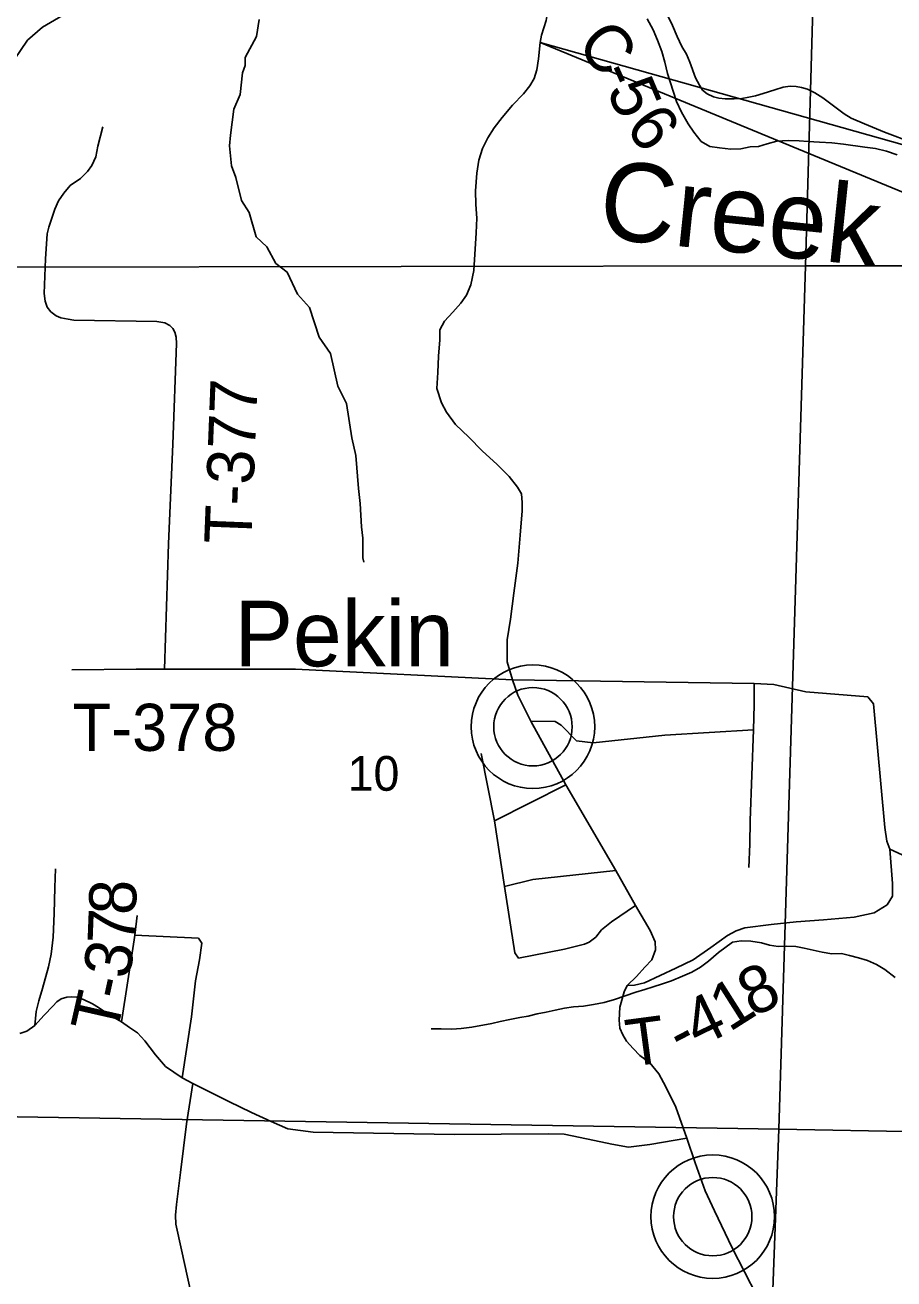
# Model space of a CAD drawing. Extents: x 0 to 34, y 0 to 22.
# Drawn here: x 4.552 to 5.598, y 15.891 to 17.402 of the extents above; entities that cross this region are included whole.
import ezdxf

# ---------------------------------------------------------------- set-up
doc = ezdxf.new("R2010")
doc.units = 0
for name, color, linetype in [('GM_X_County_Road', 7, 'Continuous'), ('GM_X_County_Road_Text', 7, 'Continuous'), ('GM_X_Minor_River', 7, 'Continuous'), ('GM_X_Minor_River_Text', 7, 'Continuous'), ('GM_X_Section', 7, 'Continuous'), ('GM_X_Section_Text', 7, 'Continuous'), ('GM_X_State_Route', 7, 'Continuous'), ('GM_X_Township_Road', 7, 'Continuous'), ('GM_X_Township_Road_Text', 7, 'Continuous'), ('GM_X_Unincorporated', 7, 'Continuous'), ('GM_X_Unincorporated_Location', 7, 'Continuous'), ('GM_X_Unincorporated_Text', 7, 'Continuous'), ('SC_Shading1', 7, 'Continuous'), ('SH_Data', 7, 'Continuous')]:
    doc.layers.add(name, color=color, linetype=linetype)

msp = doc.modelspace()

# ---------------------------------------------------------------- linework, layer by layer
at = {"layer": 'GM_X_County_Road'}
for p, q in [((5.3266, 17.4121), (5.3318, 17.4013)), ((5.3318, 17.4013), (5.3373, 17.3878)), ((5.3373, 17.3878), (5.3428, 17.376)), ((5.3428, 17.376), (5.3484, 17.3665)), ((5.3484, 17.3665), (5.3526, 17.3568)), ((5.3526, 17.3568), (5.3594, 17.3382)), ((5.3594, 17.3382), (5.3641, 17.3291)), ((5.3641, 17.3291), (5.3676, 17.3233)), ((5.3676, 17.3233), (5.3735, 17.3189)), ((5.4407, 17.3191), (5.4548, 17.3238)), ((5.4548, 17.3238), (5.465, 17.3268)), ((5.465, 17.3268), (5.4735, 17.3279)), ((5.4735, 17.3279), (5.4806, 17.3278)), ((5.4806, 17.3278), (5.4868, 17.3266)), ((5.4868, 17.3266), (5.4943, 17.3243)), ((5.4943, 17.3243), (5.503, 17.3201)), ((5.3735, 17.3189), (5.3809, 17.3154)), ((5.3809, 17.3154), (5.3874, 17.3137)), ((5.3874, 17.3137), (5.3949, 17.313)), ((5.3949, 17.313), (5.406, 17.3129)), ((5.406, 17.3129), (5.4152, 17.3134)), ((5.4152, 17.3134), (5.4234, 17.3149)), ((5.4234, 17.3149), (5.4315, 17.3166)), ((5.4315, 17.3166), (5.4407, 17.3191)), ((5.503, 17.3201), (5.5127, 17.3142)), ((5.5127, 17.3142), (5.527, 17.303)), ((5.527, 17.303), (5.5382, 17.2949)), ((5.5382, 17.2949), (5.5467, 17.2894)), ((5.5467, 17.2894), (5.5628, 17.2829)), ((5.5628, 17.2829), (5.5871, 17.2728)), ((5.5871, 17.2728), (5.621, 17.2599)), ((4.5855, 16.2201), (4.5901, 16.2253)), ((4.5901, 16.2253), (4.5956, 16.2287)), ((4.5956, 16.2287), (4.6022, 16.2306)), ((4.6022, 16.2306), (4.6076, 16.2311)), ((4.6076, 16.2311), (4.6145, 16.2308)), ((4.6145, 16.2308), (4.6222, 16.2278)), ((4.6222, 16.2278), (4.6331, 16.2228)), ((4.6331, 16.2228), (4.6403, 16.2184)), ((4.5636, 16.1967), (4.5752, 16.2091)), ((4.5752, 16.2091), (4.5855, 16.2201)), ((4.6403, 16.2184), (4.6539, 16.2093)), ((4.6539, 16.2093), (4.6682, 16.2012)), ((4.5541, 16.19), (4.5636, 16.1967)), ((4.6682, 16.2012), (4.6778, 16.1943)), ((4.6778, 16.1943), (4.6875, 16.1877)), ((4.5459, 16.1869), (4.5541, 16.19)), ((4.6875, 16.1877), (4.6962, 16.1783)), ((4.6962, 16.1783), (4.7092, 16.1614)), ((4.7092, 16.1614), (4.721, 16.1473)), ((4.721, 16.1473), (4.7412, 16.1337)), ((4.7412, 16.1337), (4.7541, 16.127)), ((4.7541, 16.127), (4.7972, 16.1051)), ((4.7972, 16.1051), (4.8247, 16.0918)), ((4.8247, 16.0918), (4.8482, 16.0809)), ((4.8482, 16.0809), (4.8683, 16.0722)), ((4.8683, 16.0722), (4.899, 16.0682)), ((4.899, 16.0682), (5.0689, 16.0652)), ((5.0689, 16.0652), (5.182, 16.0663)), ((5.182, 16.0663), (5.201, 16.0659)), ((5.201, 16.0659), (5.2377, 16.0581)), ((5.2377, 16.0581), (5.2586, 16.0538)), ((5.3045, 16.0533), (5.3491, 16.0608)), ((5.2586, 16.0538), (5.2785, 16.0501)), ((5.2785, 16.0501), (5.3045, 16.0533))]:
    msp.add_line(p, q, dxfattribs=at)
at = {"layer": 'GM_X_Minor_River'}
for p, q in [((4.642, 17.4397), (4.5728, 17.3993)), ((4.5728, 17.3993), (4.5549, 17.3834)), ((4.8338, 17.4082), (4.8308, 17.388)), ((5.3082, 17.3961), (5.301, 17.4092)), ((4.5549, 17.3834), (4.5387, 17.36)), ((4.8308, 17.388), (4.8172, 17.3627)), ((5.3136, 17.3833), (5.3082, 17.3961)), ((5.3189, 17.3698), (5.3136, 17.3833)), ((5.3224, 17.357), (5.3189, 17.3698)), ((4.8172, 17.3627), (4.817, 17.3528)), ((5.3258, 17.3434), (5.3224, 17.357)), ((4.8138, 17.344), (4.8112, 17.318)), ((4.817, 17.3528), (4.8138, 17.344)), ((5.3288, 17.3332), (5.3258, 17.3434)), ((5.3364, 17.3098), (5.3288, 17.3332)), ((4.8112, 17.318), (4.8036, 17.3004)), ((5.3425, 17.2967), (5.3364, 17.3098)), ((4.8036, 17.3004), (4.7992, 17.2691)), ((5.3505, 17.2828), (5.3425, 17.2967)), ((5.3573, 17.2727), (5.3505, 17.2828)), ((4.7992, 17.2691), (4.7983, 17.2562)), ((5.3663, 17.2616), (5.3573, 17.2727)), ((5.4709, 17.2626), (5.4572, 17.2618)), ((5.4842, 17.2622), (5.4709, 17.2626)), ((4.7983, 17.2562), (4.8006, 17.2322)), ((5.3768, 17.2554), (5.3663, 17.2616)), ((5.3882, 17.2539), (5.3768, 17.2554)), ((5.402, 17.2521), (5.3882, 17.2539)), ((5.4141, 17.2528), (5.402, 17.2521)), ((5.4251, 17.2551), (5.4141, 17.2528)), ((5.4353, 17.2554), (5.4251, 17.2551)), ((5.4455, 17.2587), (5.4353, 17.2554)), ((5.4572, 17.2618), (5.4455, 17.2587)), ((5.4949, 17.2614), (5.4842, 17.2622)), ((5.5086, 17.2607), (5.4949, 17.2614)), ((5.5234, 17.2597), (5.5086, 17.2607)), ((5.5375, 17.2582), (5.5234, 17.2597)), ((5.5631, 17.2548), (5.5375, 17.2582)), ((5.5761, 17.2529), (5.5631, 17.2548)), ((5.5895, 17.2496), (5.5761, 17.2529)), ((5.6022, 17.2454), (5.5895, 17.2496)), ((4.8006, 17.2322), (4.8057, 17.2182)), ((4.8057, 17.2182), (4.8126, 17.1905)), ((4.8126, 17.1905), (4.8219, 17.1758)), ((4.8219, 17.1758), (4.8304, 17.1467)), ((4.8304, 17.1467), (4.8431, 17.1347)), ((4.8431, 17.1347), (4.854, 17.1143)), ((4.854, 17.1143), (4.8678, 17.1039)), ((4.8678, 17.1039), (4.8799, 17.0775)), ((4.8799, 17.0775), (4.8946, 17.0613)), ((4.8946, 17.0613), (4.9062, 17.0257)), ((4.9062, 17.0257), (4.9197, 17.0062)), ((4.9197, 17.0062), (4.9287, 16.9667)), ((4.9287, 16.9667), (4.9389, 16.946)), ((4.9389, 16.946), (4.9456, 16.9046)), ((4.9456, 16.9046), (4.9505, 16.8833)), ((4.9505, 16.8833), (4.9535, 16.8434)), ((4.9535, 16.8434), (4.9557, 16.8256)), ((4.9557, 16.8256), (4.9573, 16.7974)), ((4.9573, 16.7974), (4.9587, 16.7837)), ((4.9587, 16.7837), (4.9587, 16.7598)), ((4.9587, 16.7598), (4.9599, 16.7548)), ((5.4039, 16.2971), (5.3872, 16.2847)), ((5.4145, 16.2985), (5.4039, 16.2971)), ((5.4259, 16.2981), (5.4145, 16.2985)), ((5.4389, 16.2963), (5.4259, 16.2981)), ((5.4485, 16.2935), (5.4389, 16.2963)), ((5.3872, 16.2847), (5.375, 16.2741)), ((5.4588, 16.2919), (5.4485, 16.2935)), ((5.4687, 16.2922), (5.4588, 16.2919)), ((5.4801, 16.2918), (5.4687, 16.2922)), ((5.4901, 16.2898), (5.4801, 16.2918)), ((5.5012, 16.2875), (5.4901, 16.2898)), ((5.5119, 16.2848), (5.5012, 16.2875)), ((5.5237, 16.2829), (5.5119, 16.2848)), ((5.5351, 16.2833), (5.5237, 16.2829)), ((5.5447, 16.2809), (5.5351, 16.2833)), ((5.5558, 16.2782), (5.5447, 16.2809)), ((5.3653, 16.2669), (5.3549, 16.2609)), ((5.375, 16.2741), (5.3653, 16.2669)), ((5.5665, 16.2751), (5.5558, 16.2782)), ((5.5773, 16.2701), (5.5665, 16.2751)), ((5.5874, 16.2643), (5.5773, 16.2701)), ((5.3305, 16.2506), (5.3196, 16.2469)), ((5.3436, 16.256), (5.3305, 16.2506)), ((5.3549, 16.2609), (5.3436, 16.256)), ((5.5999, 16.2544), (5.5874, 16.2643)), ((5.2876, 16.2367), (5.2748, 16.2325)), ((5.2985, 16.2401), (5.2876, 16.2367)), ((5.3083, 16.2431), (5.2985, 16.2401)), ((5.3196, 16.2469), (5.3083, 16.2431)), ((5.2367, 16.2218), (5.2246, 16.2199)), ((5.2492, 16.2245), (5.2367, 16.2218)), ((5.262, 16.2279), (5.2492, 16.2245)), ((5.2748, 16.2325), (5.262, 16.2279)), ((5.1479, 16.2061), (5.1358, 16.2039)), ((5.1577, 16.208), (5.1479, 16.2061)), ((5.1686, 16.2106), (5.1577, 16.208)), ((5.1796, 16.2128), (5.1686, 16.2106)), ((5.1902, 16.2151), (5.1796, 16.2128)), ((5.2015, 16.2177), (5.1902, 16.2151)), ((5.2125, 16.2192), (5.2015, 16.2177)), ((5.2246, 16.2199), (5.2125, 16.2192)), ((5.0433, 16.1926), (5.0411, 16.1925)), ((5.0532, 16.1925), (5.0433, 16.1926)), ((5.0658, 16.1922), (5.0532, 16.1925)), ((5.0772, 16.1929), (5.0658, 16.1922)), ((5.09, 16.1948), (5.0772, 16.1929)), ((5.1139, 16.199), (5.09, 16.1948)), ((5.124, 16.2016), (5.1139, 16.199)), ((5.1358, 16.2039), (5.124, 16.2016))]:
    msp.add_line(p, q, dxfattribs=at)
at = {"layer": 'GM_X_Section'}
for p, q in [((5.5198, 18.1024), (5.492, 17.1117)), ((5.492, 17.1117), (5.5198, 18.1024)), ((5.492, 17.1117), (4.4928, 17.1099)), ((4.4928, 17.1099), (5.492, 17.1117)), ((5.492, 17.1117), (5.4597, 16.0717)), ((5.4597, 16.0717), (5.492, 17.1117)), ((6.4366, 17.1114), (5.492, 17.1117)), ((5.492, 17.1117), (6.4366, 17.1114)), ((5.4597, 16.0717), (4.4591, 16.088)), ((4.4591, 16.088), (5.4597, 16.0717)), ((5.4597, 16.0717), (5.4229, 15.0756)), ((5.4229, 15.0756), (5.4597, 16.0717)), ((6.4161, 16.0534), (5.4597, 16.0717)), ((5.4597, 16.0717), (6.4161, 16.0534))]:
    msp.add_line(p, q, dxfattribs=at)
at = {"layer": 'GM_X_State_Route'}
for p, q in [((5.1737, 17.3895), (5.1794, 17.407)), ((5.1721, 17.3806), (5.1737, 17.3895)), ((5.1702, 17.3611), (5.1721, 17.3806)), ((5.1682, 17.3477), (5.1702, 17.3611)), ((5.1649, 17.3375), (5.1682, 17.3477)), ((5.1521, 17.3188), (5.1597, 17.3283)), ((5.1597, 17.3283), (5.1649, 17.3375)), ((5.1389, 17.3052), (5.1521, 17.3188)), ((5.1267, 17.2904), (5.1389, 17.3052)), ((5.1093, 17.2659), (5.117, 17.2778)), ((5.117, 17.2778), (5.1267, 17.2904)), ((5.103, 17.2531), (5.1093, 17.2659)), ((5.0984, 17.239), (5.103, 17.2531)), ((5.0962, 17.2232), (5.0984, 17.239)), ((5.0945, 17.2019), (5.0962, 17.2232)), ((5.095, 17.1857), (5.0945, 17.2019)), ((5.0962, 17.1691), (5.095, 17.1857)), ((5.0954, 17.1513), (5.0962, 17.1691)), ((5.0923, 17.106), (5.0954, 17.1513)), ((5.0887, 17.0888), (5.0923, 17.106)), ((5.0836, 17.0762), (5.0887, 17.0888)), ((5.0671, 17.0558), (5.0768, 17.0667)), ((5.0768, 17.0667), (5.0836, 17.0762)), ((5.0569, 17.0452), (5.0671, 17.0558)), ((5.0516, 17.0347), (5.0569, 17.0452)), ((5.0498, 17.0028), (5.0514, 17.0224)), ((5.0514, 17.0224), (5.0516, 17.0347)), ((5.049, 16.9831), (5.0498, 17.0028)), ((5.0479, 16.9641), (5.049, 16.9831)), ((5.0534, 16.9467), (5.0479, 16.9641)), ((5.0595, 16.9353), (5.0534, 16.9467)), ((5.0704, 16.9205), (5.0595, 16.9353)), ((5.0863, 16.9054), (5.0704, 16.9205)), ((5.1025, 16.8889), (5.0863, 16.9054)), ((5.1206, 16.8725), (5.1025, 16.8889)), ((5.135, 16.8581), (5.1206, 16.8725)), ((5.145, 16.8452), (5.135, 16.8581)), ((5.1498, 16.8371), (5.145, 16.8452)), ((5.1507, 16.8268), (5.1498, 16.8371)), ((5.1507, 16.8166), (5.1507, 16.8268)), ((5.1483, 16.7874), (5.1507, 16.8166)), ((5.1452, 16.7535), (5.1483, 16.7874)), ((5.1406, 16.7175), (5.1452, 16.7535)), ((5.1386, 16.7018), (5.1406, 16.7175)), ((5.1367, 16.6861), (5.1386, 16.7018)), ((5.1324, 16.6612), (5.1367, 16.6861)), ((5.1326, 16.6346), (5.1324, 16.6612)), ((5.1389, 16.613), (5.1326, 16.6346)), ((5.1454, 16.5944), (5.1389, 16.613)), ((5.1612, 16.5634), (5.1454, 16.5944)), ((5.2031, 16.4864), (5.1612, 16.5634)), ((5.2634, 16.3835), (5.2031, 16.4864)), ((5.2871, 16.3411), (5.2634, 16.3835)), ((5.3047, 16.3112), (5.2871, 16.3411)), ((5.3107, 16.2975), (5.3047, 16.3112)), ((5.3112, 16.2877), (5.3107, 16.2975)), ((5.3066, 16.2757), (5.3112, 16.2877)), ((5.2881, 16.2558), (5.2982, 16.2669)), ((5.2982, 16.2669), (5.3066, 16.2757)), ((5.2771, 16.2448), (5.2881, 16.2558)), ((5.2684, 16.2187), (5.2736, 16.2371)), ((5.2736, 16.2371), (5.2771, 16.2448)), ((5.2673, 16.2031), (5.2684, 16.2187)), ((5.2684, 16.1933), (5.2673, 16.2031)), ((5.2718, 16.1854), (5.2684, 16.1933)), ((5.2761, 16.1777), (5.2718, 16.1854)), ((5.2841, 16.1688), (5.2761, 16.1777)), ((5.2923, 16.1604), (5.2841, 16.1688)), ((5.3045, 16.1518), (5.2923, 16.1604)), ((5.3153, 16.1383), (5.3045, 16.1518)), ((5.3236, 16.1228), (5.3153, 16.1383)), ((5.3357, 16.0984), (5.3236, 16.1228)), ((5.3491, 16.0608), (5.3357, 16.0984)), ((5.359, 16.0313), (5.3491, 16.0608)), ((5.3708, 15.9975), (5.359, 16.0313)), ((5.3822, 15.9735), (5.3708, 15.9975)), ((5.4036, 15.9288), (5.3822, 15.9735)), ((5.4333, 15.8712), (5.4036, 15.9288))]:
    msp.add_line(p, q, dxfattribs=at)
at = {"layer": 'GM_X_Township_Road'}
for p, q in [((4.6397, 17.2557), (4.6457, 17.279)), ((4.6373, 17.243), (4.6397, 17.2557)), ((4.6272, 17.2254), (4.6324, 17.2326)), ((4.6324, 17.2326), (4.6373, 17.243)), ((4.6062, 17.2083), (4.6186, 17.217)), ((4.6186, 17.217), (4.6272, 17.2254)), ((4.5987, 17.1993), (4.6062, 17.2083)), ((4.5877, 17.1799), (4.5923, 17.1899)), ((4.5923, 17.1899), (4.5987, 17.1993)), ((4.5805, 17.1584), (4.5877, 17.1799)), ((4.5787, 17.1504), (4.5805, 17.1584)), ((4.5765, 17.1201), (4.5787, 17.1504)), ((4.5751, 17.0782), (4.5765, 17.1201)), ((4.5761, 17.0691), (4.5751, 17.0782)), ((4.5785, 17.0619), (4.5761, 17.0691)), ((4.5829, 17.0561), (4.5785, 17.0619)), ((4.5893, 17.0513), (4.5829, 17.0561)), ((4.5949, 17.0491), (4.5893, 17.0513)), ((4.6038, 17.0473), (4.5949, 17.0491)), ((4.6106, 17.0463), (4.6038, 17.0473)), ((4.7105, 17.0445), (4.6106, 17.0463)), ((4.7205, 17.0429), (4.7105, 17.0445)), ((4.7263, 17.0399), (4.7205, 17.0429)), ((4.7301, 17.036), (4.7263, 17.0399)), ((4.7325, 17.0316), (4.7301, 17.036)), ((4.7339, 17.0258), (4.7325, 17.0316)), ((4.7345, 17.0182), (4.7339, 17.0258)), ((4.7299, 16.8968), (4.7345, 17.0182)), ((4.7249, 16.7769), (4.7299, 16.8968)), ((4.7199, 16.6259), (4.7249, 16.7769)), ((4.6084, 16.625), (4.6858, 16.6257)), ((4.6858, 16.6257), (4.7018, 16.6259)), ((4.7018, 16.6259), (4.7199, 16.6259)), ((4.7199, 16.6259), (4.7998, 16.6259)), ((4.7998, 16.6259), (4.8777, 16.626)), ((4.8777, 16.626), (5.1389, 16.613)), ((5.1389, 16.613), (5.4299, 16.6088)), ((5.4299, 16.6088), (5.4537, 16.6073)), ((5.4299, 16.5831), (5.4299, 16.6088)), ((5.4537, 16.6073), (5.4922, 16.5985)), ((5.4922, 16.5985), (5.5669, 16.5927)), ((5.429, 16.5529), (5.4299, 16.5831)), ((5.5669, 16.5927), (5.5735, 16.584)), ((5.5735, 16.584), (5.5875, 16.4351)), ((5.1612, 16.5634), (5.1902, 16.5627)), ((5.1902, 16.5627), (5.1974, 16.5586)), ((5.1974, 16.5586), (5.216, 16.5394)), ((5.3225, 16.5464), (5.429, 16.5529)), ((5.4251, 16.4434), (5.429, 16.5529)), ((5.216, 16.5394), (5.2363, 16.537)), ((5.2363, 16.537), (5.3225, 16.5464)), ((5.1173, 16.4432), (5.1012, 16.5243)), ((5.1173, 16.4432), (5.2031, 16.4864)), ((5.1293, 16.3639), (5.1173, 16.4432)), ((5.4248, 16.415), (5.4251, 16.4434)), ((5.5875, 16.4351), (5.5899, 16.4186)), ((5.5899, 16.4186), (5.5932, 16.4089)), ((5.4236, 16.387), (5.4248, 16.415)), ((5.5932, 16.4089), (5.7455, 16.3395)), ((5.5967, 16.3678), (5.5932, 16.4089)), ((4.5879, 16.3629), (4.5888, 16.3855)), ((5.1293, 16.3639), (5.1634, 16.3725)), ((5.1634, 16.3725), (5.2634, 16.3835)), ((4.5871, 16.3315), (4.5879, 16.3629)), ((5.1418, 16.2841), (5.1293, 16.3639)), ((5.5964, 16.3524), (5.5967, 16.3678)), ((5.2871, 16.3411), (5.2583, 16.3215)), ((5.5744, 16.3325), (5.5901, 16.3419)), ((5.5901, 16.3419), (5.5964, 16.3524)), ((4.5859, 16.3032), (4.5871, 16.3315)), ((4.6842, 16.3056), (4.6871, 16.3292)), ((5.5133, 16.3238), (5.5503, 16.3271)), ((5.5503, 16.3271), (5.5744, 16.3325)), ((5.246, 16.3118), (5.2392, 16.3032)), ((5.2583, 16.3215), (5.246, 16.3118)), ((5.4083, 16.3108), (5.4186, 16.3144)), ((5.4186, 16.3144), (5.4503, 16.3182)), ((5.4503, 16.3182), (5.4804, 16.3217)), ((5.4804, 16.3217), (5.5133, 16.3238)), ((4.5834, 16.2827), (4.5859, 16.3032)), ((4.6682, 16.2012), (4.6833, 16.2997)), ((4.6833, 16.2997), (4.6842, 16.3056)), ((4.6842, 16.3056), (4.761, 16.3019)), ((4.765, 16.2957), (4.761, 16.3019)), ((5.2312, 16.2972), (5.2257, 16.2946)), ((5.2392, 16.3032), (5.2312, 16.2972)), ((5.3777, 16.2907), (5.3979, 16.3051)), ((5.3979, 16.3051), (5.4083, 16.3108)), ((4.5802, 16.2675), (4.5834, 16.2827)), ((4.7621, 16.2759), (4.765, 16.2957)), ((5.1462, 16.2778), (5.1418, 16.2841)), ((5.2016, 16.2887), (5.1462, 16.2778)), ((5.2257, 16.2946), (5.2016, 16.2887)), ((5.3564, 16.2759), (5.3777, 16.2907)), ((4.5728, 16.2411), (4.5802, 16.2675)), ((4.7572, 16.2503), (4.7621, 16.2759)), ((5.2979, 16.248), (5.3358, 16.2657)), ((5.3358, 16.2657), (5.3564, 16.2759)), ((4.5686, 16.2264), (4.5728, 16.2411)), ((4.7526, 16.207), (4.7572, 16.2503)), ((5.2771, 16.2448), (5.2858, 16.2452)), ((5.2858, 16.2452), (5.2979, 16.248)), ((4.5654, 16.2136), (4.5686, 16.2264)), ((4.5636, 16.1967), (4.5654, 16.2136)), ((4.7412, 16.1337), (4.7526, 16.207)), ((4.7466, 16.0782), (4.7541, 16.127)), ((4.739, 16.0194), (4.7466, 16.0782)), ((4.7342, 15.981), (4.739, 16.0194)), ((4.733, 15.9683), (4.7342, 15.981)), ((4.7335, 15.9573), (4.733, 15.9683)), ((4.7405, 15.9263), (4.7335, 15.9573)), ((4.7565, 15.8529), (4.7405, 15.9263))]:
    msp.add_line(p, q, dxfattribs=at)
at = {"layer": 'GM_X_Unincorporated'}
for centre, radius in [((5.1636, 16.5565), 0.0744), ((5.1636, 16.5565), 0.0472), ((5.3801, 15.9664), 0.0744), ((5.3801, 15.9664), 0.0472)]:
    msp.add_circle(centre, radius, dxfattribs=at)
at = {"layer": 'GM_X_Unincorporated_Location'}
for p, q in [((5.1636, 16.5565), (5.1636, 16.5565)), ((5.3801, 15.9664), (5.3801, 15.9664))]:
    msp.add_line(p, q, dxfattribs=at)
at = {"layer": 'SC_Shading1'}
msp.add_lwpolyline([(10.3861, 15.9111), (10.3861, 15.2276), (5.1721, 17.3806)], close=True, dxfattribs=at)
at = {"layer": 'SH_Data'}
msp.add_line((5.1737, 17.3895), (5.1721, 17.3806), dxfattribs=at)
for points in [[(5.1737, 17.3895), (5.1794, 17.407), (5.1794, 17.407), (5.1812, 17.4169), (5.1799, 17.4258), (5.1769, 17.4324), (5.1702, 17.4396), (5.1662, 17.4432), (5.1624, 17.4455), (5.1535, 17.4507), (5.1418, 17.4552), (5.1296, 17.4574), (5.1222, 17.4586), (5.1076, 17.4611), (5.1047, 17.4616), (5.0983, 17.4634), (5.0918, 17.4648), (5.0783, 17.4676)], [(10.3861, 15.9111), (5.1721, 17.3806), (10.3861, 15.2276)]]:
    msp.add_lwpolyline(points, dxfattribs=at)

# ---------------------------------------------------------------- texts
at = {"layer": 'GM_X_County_Road_Text'}
for s, rotation, p in [('C', 310.9535, (5.2143, 17.3766)), ('5', 292.8925, (5.2519, 17.324)), ('-', 293.9704, (5.2425, 17.3451)), ('6', 307.4157, (5.2734, 17.2782))]:
    msp.add_text(s, height=0.0568, rotation=rotation, dxfattribs=at).set_placement(p)
at = {"layer": 'GM_X_Minor_River_Text'}
msp.add_text('Creek', height=0.0947, rotation=354.0791, dxfattribs=at).set_placement((5.2404, 17.1456))
at = {"layer": 'GM_X_Section_Text'}
msp.add_text('10', height=0.04186, rotation=0, dxfattribs=at).set_placement((4.9405, 16.4794))
at = {"layer": 'GM_X_Township_Road_Text'}
for s, height, rotation, p in [('T-377', 0.05682, 87.755, (4.8244, 16.7758)), ('T-378', 0.05682, 0, (4.6092, 16.5274)), ('8', 0.0568, 88.0149, (4.6853, 16.3292)), ('7', 0.0568, 87.8139, (4.6839, 16.294)), ('3', 0.0568, 80.2124, (4.6771, 16.2514)), ('8', 0.0568, 25.7086, (5.428, 16.206)), ('-', 0.0568, 77.5076, (4.6715, 16.2257)), ('T', 0.0568, 77.1955, (4.662, 16.184)), ('1', 0.0568, 32.3771, (5.4, 16.1881)), ('4', 0.0568, 25.9343, (5.3624, 16.1694)), ('T', 0.0568, 7.6252, (5.2795, 16.1467)), ('-', 0.0568, 27.5351, (5.3421, 16.1588))]:
    msp.add_text(s, height=height, rotation=rotation, dxfattribs=at).set_placement(p)
at = {"layer": 'GM_X_Unincorporated_Text'}
msp.add_text('Pekin', height=0.07898, rotation=0, dxfattribs=at).set_placement((4.8042, 16.6293))

doc.saveas('drawing.dxf')
